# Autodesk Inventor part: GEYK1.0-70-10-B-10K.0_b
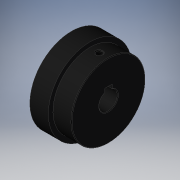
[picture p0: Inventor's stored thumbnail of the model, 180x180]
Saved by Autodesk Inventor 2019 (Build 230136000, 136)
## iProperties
Created: 2022-11
Part Number: GEYK1.0-70-10-B-10K.0_b
Material: Generic
Catalog Web Link: www.cadenas.de
Description: GEY_body-Plastic Bonded Spur Gears
Vendor: MISUMI
Document SubType Name: Modeling
Designer: psAdmin
Manufacturer: MISUMI
Mass: 26.6277 g
Surface Area: 64.7379 cm^2
Volume: 26.6277 cm^3
Density: 1 g/cm^3
Appearance: PSOLRGB-128-128-128
Category: PARTsolutions
Company: MISUMI
Title: GEYK1.0-70-10-B-10K.0
Author: Cadenas PARTsolutions
Comments: Plastic Bonded Spur Gears
PSOL_IDENT_0: {$CADENAS_DATA/23d-libs/misumi/metric/54_spur_gears/gey_.prj},213 {VTYP=3D},{NB=GEYK1.0-70-10-B-10K.
PSOL_IDENT_1: 0_b},{LINA=GEYK1.0-70-10-B-10K.0},{NN=GEY_body},{DATE=07.06.2021 01:25:59},{GEOMDATE=23.08.2016 05:0
PSOL_IDENT_2: 9:00},{VERSION=},{LINEID=10},{WBVAR=SHS,NT,PS,ALT1,ALT2,BS},{WBNUMERIC=NT,BS}  {NB=GEYK1.0-70-10-B-1
PSOL_IDENT_3: 0K.0_b},{LINA=GEYK1.0-70-10-B-10K.0},{KT=DUMMY},{PN=GEYK1.0-70-10-B-10K.0},{SHS=K},{SHSPN=K},{GEAKBH=
PSOL_IDENT_4: 0},{MAT=MC Nylon},{MATC=S25C},{AC=Set Screw},{MOD=1.0},{NT=70},{NTA=30,32,34,35,36,38,40,42,45,48,50
PSOL_IDENT_5: ,52,56,60,70,75},{B=10},{TS=B},{TSA='B','B'},{PS=10K},{PSA= '10N','10N','10K','10K','11N','11N','12N'
PSOL_IDENT_6: ,'12N','13N','13N','14N','14N','15N','15N','16N','16N','17N','17N','18N','18N','19N','19N','20N','20
PSOL_IDENT_7: N','21N','21N','22N','22N','23N','23N','24N','24N'},{PS1= '10','10','11','11','12','12','13','13','1
PSOL_IDENT_8: 4','14','15','15','16','16','17','17','18','18','19','19','20','20','21','21','22','22','23','23','2
PSOL_IDENT_9: 4','24','25','25','26','26','27','27','28','28'},{PS2= '10N','10N','10K','10K','11N','11N','12N','12
PSOL_IDENT_10: N','13N','13N','14N','14N','15N','15N','16N','16N','17N','17N','18N','18N','19N','19N','20N','20N','
PSOL_IDENT_11: 21N','21N','22N','22N','23N','23N','24N','24N'},{P=10.00},{DD=70.0},{D=72.0},{H=40},{E=45},{L=20},{L
PSOL_IDENT_12: L1=10},{LL2=5.000},{M=M4},{M2=4},{ACSS=M4x3},{TT=1.8},{BB=4},{ALT1=},{ALTA='','w/o Set Screw', '-KC9
PSOL_IDENT_13: 0', 'with KC90 (Set Screw)', '-KC120', 'with KC120 (Set Screw)'},{SCREWL=3},{PLANE=20},{PLANE1=20},{
PSOL_IDENT_14: ALT2=},{ALT2A='','w/o Boss Cut','-BS','with BS (Boss Cut)'},{BS=0.0},{BSA=0},{BSMIN=7.0},{BSMAX=9.5}
PSOL_IDENT_15: ,{HD=15.000}
NB: GEYK1.0-70-10-B-10K.0_b
NN: GEY_body
NT: 70
NBSYN: $PN._b
LINA: GEYK1.0-70-10-B-10K.0
CATALOG: Misumi
PN: GEYK1.0-70-10-B-10K.0
SHS: Key Groove Hole+Tap
MAT: MC Nylon
MATC: S25C
MOD: 1.0
B: 10
PS: 10K
L: 20
LL1: 10
ALT1: w/o Set Screw
ALT2: w/o Boss Cut
BS: 0
SUPPLIER: MISUMI
ARTICLENO: GEYK1.0-70-10-B-10K.0_b
BOMINFO: GEYK1.0-70-10-B-10K.0
CREATOR: CADENAS GmbH
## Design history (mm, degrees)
sketch "Sketch_11"
  geometry: L1 (20, 0)-(0, 0); L2 (0, 0)-(0, 34); L3 (0, 34)-(0.536, 36); L4 (0.536, 36)-(9.464, 36); L5 (9.464, 36)-(10, 34); L6 (10, 34)-(10, 20); L7 (10, 20)-(19.7, 20); L8 (19.7, 20)-(20, 19.7); L9 (20, 19.7)-(20, 0); L10 (20, 0)-(0, 0)
  constraints: 20 end point
revolve "Revolution1" sketch "Sketch_11" stored, may be unused: angle "d0" = 360 deg
sketch "Sketch_2"
  geometry: C1 r 41 at (0, 0); C2 r 22.5 at (0, 0); 2 further points
  constraints: 2 centre point
extrude "Extrusion1" cut sketch "Sketch_2" distance "d1" = 10; taper "d2" = 0 deg
sketch "_____1"
  geometry: L1 (40, 0)-(-40, 0); L2 (0, 0)-(0, 5.3); L3 (0, 5.3)-(0.3, 5); L4 (0.3, 5)-(19.7, 5); L5 (19.7, 5)-(20, 5.3); L6 (20, 5.3)-(20, 0); L7 (20, 0)-(0, 0)
  constraints: 14 end point
revolve "Revolution2" sketch "_____1" stored, may be unused: angle "d3" = 360 deg
sketch "Sketch_3"
  geometry: L1 (15, 0)-(15, 21); L2 (15, 21)-(17, 21); L3 (17, 21)-(17, 20); L4 (17, 20)-(16.621, 19.621); L5 (16.621, 19.621)-(16.621, 0); L6 (16.621, 0)-(15, 0); L7 (15, 0)-(15, 21)
  constraints: 14 end point
revolve "Revolution3" sketch "Sketch_3" stored, may be unused: angle "d4" = 360 deg
thread "Thread1" dims "d5" = 15.0384, "d6" = 0
sketch "Sketch_5"
  geometry: L1 (6.6, 2)-(0, 2); L2 (0, 2)-(0, -2); L3 (0, -2)-(6.6, -2); L4 (6.8, -1.8)-(6.8, 1.8); A1 r 0.2 centre (6.6, -1.8) between (6.6, -2) and (6.8, -1.8); A2 r 0.2 centre (6.6, 1.8) between (6.8, 1.8) and (6.6, 2)
  constraints: 8 end point, 4 point on circle, 2 centre point
extrude "Extrusion2" cut sketch "Sketch_5" distance "d7" = 20; taper "d8" = 0 deg
node "body_to_teeth_XY"
node "body_to_teeth_YZ"
node "body_to_teeth_ZX"
node "body_to_teeth_X"
node "body_to_teeth_Y"
node "body_to_teeth_Z"
node "body_to_teeth_Center"
node "screw1_XY"
node "screw1_YZ"
node "screw1_ZX"
node "screw1_X"
node "screw1_Y"
node "screw1_Z"
node "screw1_Center"
node "screw2_XY"
node "screw2_YZ"
node "screw2_ZX"
node "screw2_X"
node "screw2_Y"
node "screw2_Z"
node "screw2_Center"
node "screw3_XY"
node "screw3_YZ"
node "screw3_ZX"
node "screw3_X"
node "screw3_Y"
node "screw3_Z"
node "screw3_Center"
body "Solid1"
other parameters: "d9" = 0
